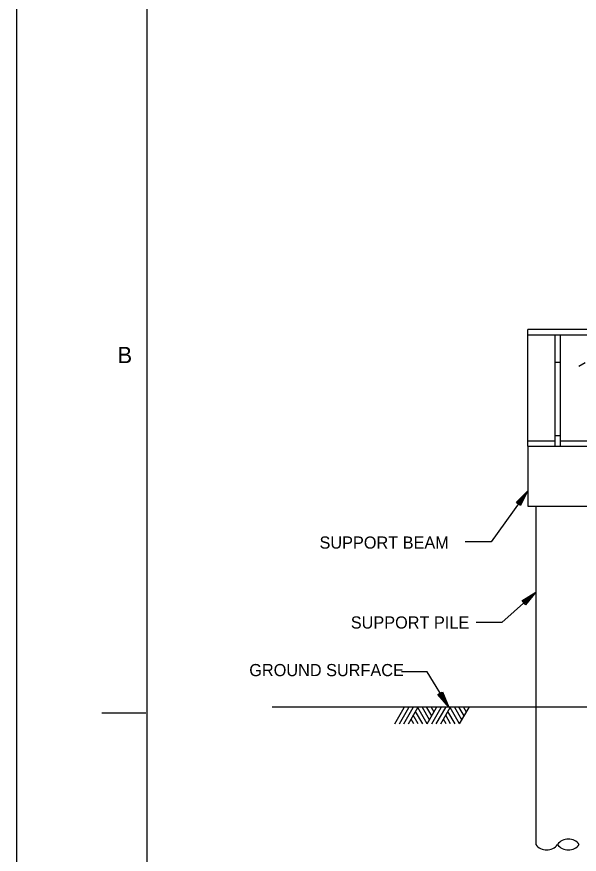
# Model space of a CAD drawing. Extents: x 22369.6 to 22413.6, y 22369.6 to 22403.6.
# Drawn here: x 22369.62 to 22376.09, y 22376.74 to 22386.37 of the extents above; entities that cross this region are included whole.
import ezdxf

# ---------------------------------------------------------------- set-up
doc = ezdxf.new("R2010")
doc.units = 0
for name, color, linetype in [('Level 1', 7, 'Continuous'), ('Level 10', 7, 'Continuous'), ('Level 2', 7, 'Continuous'), ('Level 4', 7, 'Continuous'), ('Level 7', 7, 'Continuous'), ('Level 9', 7, 'Continuous')]:
    doc.layers.add(name, color=color, linetype=linetype)

msp = doc.modelspace()

# ---------------------------------------------------------------- linework, layer by layer
at = {"layer": 'Level 1'}
for p, q in [((22376.09, 22382.3536), (22376.1598, 22382.3986)), ((22375.4698, 22380.8792), (22375.4698, 22380.8792)), ((22375.5001, 22380.9214), (22375.5001, 22380.9214)), ((22375.5551, 22379.7221), (22375.5551, 22379.7221)), ((22375.5938, 22379.7568), (22375.5938, 22379.7568)), ((22374.5647, 22378.4781), (22374.5647, 22378.4781)), ((22373.972, 22378.2415), (22374.0802, 22378.429)), ((22374.024, 22378.2415), (22374.1322, 22378.429)), ((22374.076, 22378.2415), (22374.1842, 22378.429)), ((22374.1279, 22378.2415), (22374.2361, 22378.429)), ((22374.2924, 22378.2415), (22374.2101, 22378.384)), ((22374.3444, 22378.2415), (22374.2361, 22378.429)), ((22374.3704, 22378.2865), (22374.2881, 22378.429)), ((22374.3964, 22378.3315), (22374.3401, 22378.429)), ((22374.3444, 22378.2415), (22374.4526, 22378.4288)), ((22374.4224, 22378.3765), (22374.3921, 22378.429)), ((22374.3964, 22378.2415), (22374.5047, 22378.429)), ((22374.4482, 22378.2415), (22374.5566, 22378.429)), ((22374.5002, 22378.2415), (22374.6086, 22378.429)), ((22374.6649, 22378.2415), (22374.5826, 22378.384)), ((22374.5919, 22378.4337), (22374.5919, 22378.4337)), ((22374.7169, 22378.2415), (22374.6086, 22378.429)), ((22374.7429, 22378.2865), (22374.6606, 22378.429)), ((22374.7689, 22378.3315), (22374.7126, 22378.429)), ((22374.7169, 22378.2415), (22374.8252, 22378.429)), ((22374.7949, 22378.3765), (22374.7646, 22378.429)), ((22374.1885, 22378.2415), (22374.1582, 22378.294)), ((22374.2404, 22378.2415), (22374.1841, 22378.339)), ((22374.561, 22378.2415), (22374.5307, 22378.294)), ((22374.6129, 22378.2415), (22374.5566, 22378.339))]:
    msp.add_line(p, q, dxfattribs=at)
msp.add_lwpolyline([(22369.6213, 22403.6293), (22413.6217, 22403.6293), (22413.6217, 22369.6213), (22369.6213, 22369.6213)], close=True, dxfattribs=at)
for points in [[(22375.5001, 22380.9214), (22375.0785, 22380.333), (22374.7822, 22380.333)], [(22375.366, 22380.7875), (22375.5001, 22380.9214), (22375.4164, 22380.7514), (22375.3733, 22380.7822), (22375.4698, 22380.8792), (22375.4129, 22380.7637), (22375.3853, 22380.7835), (22375.4407, 22380.8385), (22375.4094, 22380.776), (22375.3981, 22380.7842), (22375.4104, 22380.7962)], [(22375.5938, 22379.7568), (22375.2044, 22379.4078), (22374.9081, 22379.4078)], [(22375.4339, 22379.6551), (22375.5938, 22379.7568), (22375.4753, 22379.6089), (22375.4399, 22379.6484), (22375.5551, 22379.7221), (22375.4745, 22379.6217), (22375.4519, 22379.647), (22375.5179, 22379.6887), (22375.4738, 22379.6345), (22375.4645, 22379.6449), (22375.4791, 22379.654)], [(22374.5919, 22378.4337), (22374.3444, 22378.8383), (22374.048, 22378.8383)], [(22374.5207, 22378.6094), (22374.5919, 22378.4337), (22374.4678, 22378.5771), (22374.5131, 22378.6047), (22374.5647, 22378.4781), (22374.4806, 22378.5755), (22374.5096, 22378.5932), (22374.5386, 22378.5208), (22374.4932, 22378.5739), (22374.5052, 22378.5812), (22374.5115, 22378.5651)]]:
    msp.add_lwpolyline(points, dxfattribs=at)
at = {"layer": 'Level 10'}
msp.add_line((22370.6017, 22378.3693), (22371.1057, 22378.3693), dxfattribs=at)
at = {"layer": 'Level 2'}
for p, q in [((22375.8126, 22382.715), (22375.8126, 22381.4337)), ((22375.8751, 22382.715), (22375.8751, 22381.4337)), ((22375.8126, 22382.4025), (22375.8751, 22382.4025)), ((22375.8126, 22381.5587), (22375.8751, 22381.5587)), ((22380.1251, 22378.4337), (22372.56, 22378.4337)), ((22375.5938, 22378.4337), (22375.5938, 22376.8528))]:
    msp.add_line(p, q, dxfattribs=at)
for centre, start, end in [((22375.9684, 22376.7592), 36.86225, 143.13775), ((22375.7187, 22376.9464), 216.8699, 323.1301), ((22375.9684, 22376.9464), 216.8699, 323.1301)]:
    msp.add_arc(centre, 0.1561, start, end, dxfattribs=at)
at = {"layer": 'Level 7'}
for p, q in [((22375.5001, 22381.4337), (22375.5001, 22382.7775)), ((22379.6094, 22382.7775), (22375.5001, 22382.7775)), ((22375.5001, 22382.715), (22379.6094, 22382.715)), ((22375.5001, 22381.4962), (22375.8126, 22381.4962)), ((22375.5001, 22381.4337), (22375.5001, 22380.7462)), ((22375.5001, 22381.4337), (22376.1876, 22381.4337)), ((22375.8751, 22381.4962), (22379.6094, 22381.4962)), ((22375.5001, 22380.7462), (22376.1876, 22380.7462)), ((22375.5938, 22380.7462), (22375.5938, 22378.4337))]:
    msp.add_line(p, q, dxfattribs=at)
at = {"layer": 'Level 9'}
msp.add_line((22371.1213, 22370.1253), (22371.1213, 22403.1253), dxfattribs=at)

# ---------------------------------------------------------------- texts
at = {"layer": 'Level 1'}
msp.add_text('B', height=0.1873, dxfattribs=at).set_placement((22370.7817, 22382.3893))
at = {"layer": 'Level 4'}
for s, p in [('SUPPORT BEAM', (22373.1051, 22380.2558)), ('SUPPORT PILE', (22373.4647, 22379.3367)), ('GROUND SURFACE', (22372.2969, 22378.7892))]:
    msp.add_text(s, height=0.14, dxfattribs=at).set_placement(p)

doc.saveas('drawing.dxf')
